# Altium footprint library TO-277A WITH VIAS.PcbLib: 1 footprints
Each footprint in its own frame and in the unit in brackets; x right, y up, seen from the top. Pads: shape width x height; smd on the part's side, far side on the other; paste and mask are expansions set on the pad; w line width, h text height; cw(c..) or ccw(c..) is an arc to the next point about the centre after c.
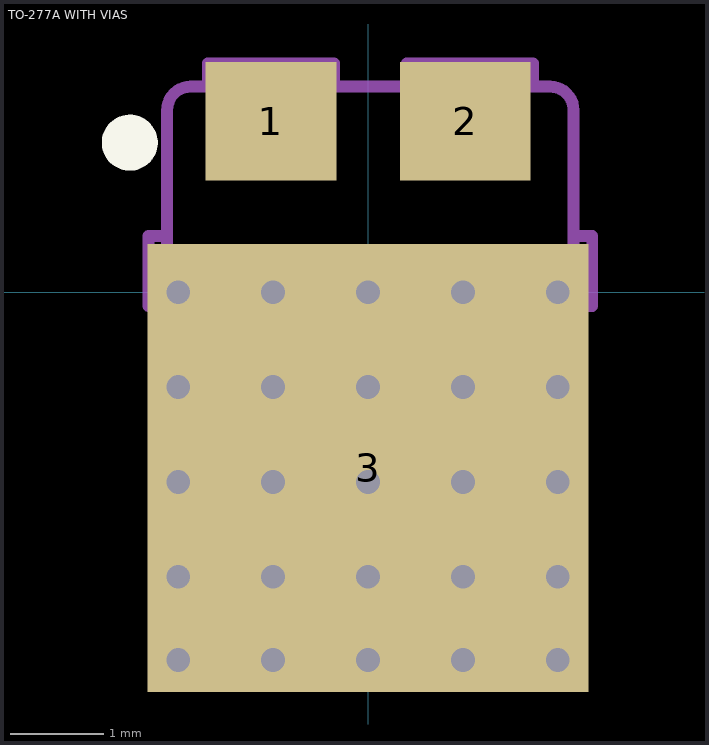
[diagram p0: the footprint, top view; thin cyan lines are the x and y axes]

## TO-277A WITH VIAS [mm] "Vishay"
height 1.2
pads (3):
  rect 1.4x1.27 smd: 1(-1.04,1.83) 2(1.04,1.83)
  rect 4.72x4.8 smd: 3(0,-1.883)
via -2.032,-3.937 diameter 0.61 hole 0.254
via -1.016,-3.937 diameter 0.61 hole 0.254
via 2.032,-3.937 diameter 0.61 hole 0.254
via 1.016,-3.937 diameter 0.61 hole 0.254
via -2.032,-3.048 diameter 0.61 hole 0.254
via -1.016,-3.048 diameter 0.61 hole 0.254
via 0,-3.048 diameter 0.61 hole 0.254
via 1.016,-3.048 diameter 0.61 hole 0.254
via 1.016,-2.032 diameter 0.61 hole 0.254
via 0,-2.032 diameter 0.61 hole 0.254
via -1.016,-2.032 diameter 0.61 hole 0.254
via -2.032,-2.032 diameter 0.61 hole 0.254
via -2.032,-1.016 diameter 0.61 hole 0.254
via -1.016,-1.016 diameter 0.61 hole 0.254
via 0,-1.016 diameter 0.61 hole 0.254
via 1.016,-1.016 diameter 0.61 hole 0.254
via 2.032,-3.048 diameter 0.61 hole 0.254
via 2.032,-2.032 diameter 0.61 hole 0.254
via 2.032,-1.016 diameter 0.61 hole 0.254
via 2.032,0 diameter 0.61 hole 0.254
via 1.016,0 diameter 0.61 hole 0.254
via -2.032,0 diameter 0.61 hole 0.254
via -1.016,0 diameter 0.61 hole 0.254
via 0,-3.937 diameter 0.61 hole 0.254
via 0,0 diameter 0.61 hole 0.254
Top Overlay:
  circle w0.3: c-2.55,1.6 r0.15
M5 Assembly Top:
  lines w0.127: -2.15,-0.15 -2.35,-0.15 -2.35,0.6 -2.15,0.6 ; -1.715,2.2 -1.715,2.45 -0.365,2.45 -0.365,2.2 ; -1.075,-3.95 -1.075,-4.2 1.125,-4.2 1.125,-3.95 ; 0.415,2.2 0.415,2.45 1.765,2.45 1.765,2.2 ; 2.2,-0.15 2.4,-0.15 2.4,0.6 2.2,0.6 ; -2.15,-3.7 ccw(c-1.9,-3.7) -1.9,-3.95 1.95,-3.95 ccw(c1.95,-3.7) 2.2,-3.7 2.2,1.95 ccw(c1.95,1.95) 1.95,2.2 -1.9,2.2 ccw(c-1.9,1.95) -2.15,1.95 -2.15,-3.7
  text ".Designator" at -1.8,-0.5 h1.02
3D body: height 1.2, standoff 0, extent -2.35,-4.2 2.4,2.45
